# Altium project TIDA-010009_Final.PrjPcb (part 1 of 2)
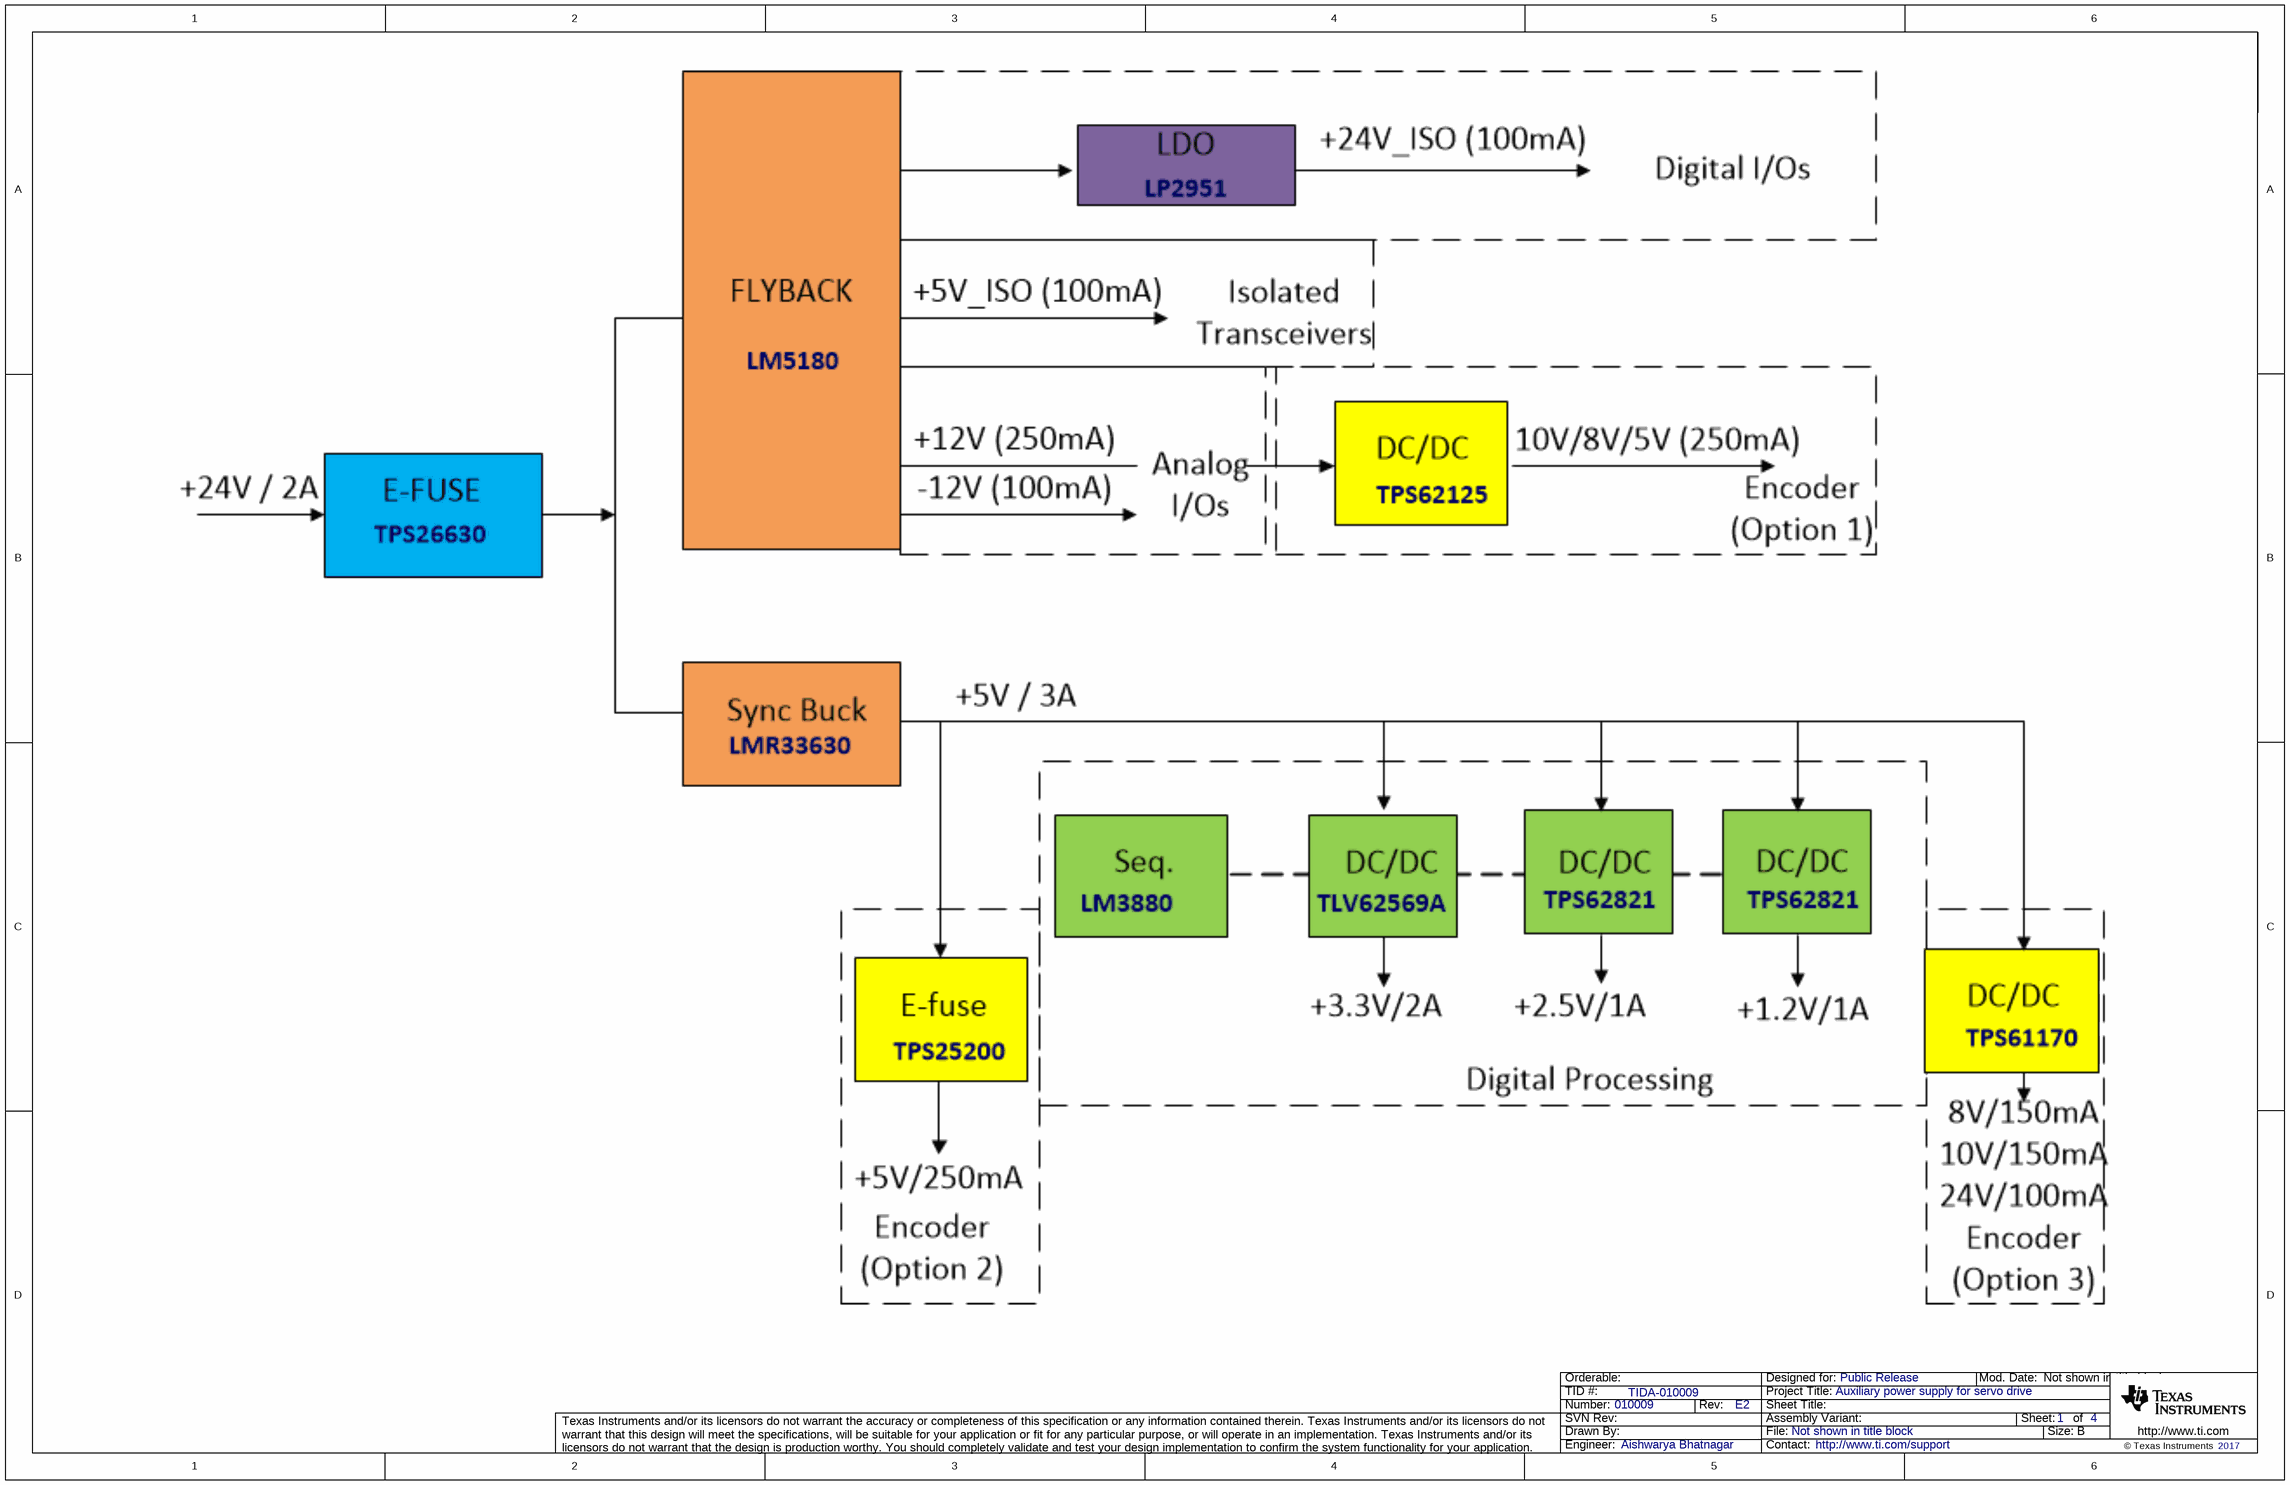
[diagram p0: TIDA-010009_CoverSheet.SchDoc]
CopyrightYear: 2017; PCB_Layout: Aishwarya; PCB_Rev: E2; PRJ_Customer: Public Release; PRJ_Engineer: Aishwarya Bhatnagar; PRJ_Number: 010009; PRJ_Title: Auxiliary power supply for servo drive; SCH_Rev: E2; TechSupport: http://www.ti.com/support; TID: TIDA-010009
4 sheets, 217 parts. Net scope: flat (ports and power ports of the same name join across sheets).
Board file: TIDA-010009_EVM_E2.PcbDoc
Sheets:
  TIDA-010009_CoverSheet.SchDoc
  Schematic1.SchDoc
  Schematic2.SchDoc
  TIDA-010009_EVM_Hardware.SchDoc

## Sheet TIDA-010009_CoverSheet.SchDoc
size 431 x 279 mm; Date: Not shown in title block; ApprovedBy: Not shown in title block; CheckedBy: Not shown in title block; Author: Not shown in title block; CompanyName: Not shown in title block; Engineer: Not shown in title block; Organization: Not shown in title block; Address1: Not shown in title block; Address2: Not shown in title block; Address3: Not shown in title block; Address4: Not shown in title block; DocumentNumber: 1; Revision: Use project parameter SCH_Rev; SheetNumber: 1; SheetTotal: 4; PageSetup: Record=PageOptions¦CenterHorizontal=True¦CenterVertical=True¦PrintScale=1.00¦XCorrection=1.00¦YCorrection=1.00¦PrintKind=0¦BorderSize=5000000¦LeftOffset=0¦BottomOffset=0¦Orientation=2¦PaperLength=1000¦PaperWidth=1000¦Scale=100¦PaperSource=15¦PrintQuality=600¦MediaType=1¦DitherType=10¦PaperKind=Letter¦PrintScaleMode=1

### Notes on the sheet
- Place Block Diagram here (if appropriate) or delete this text box.
  If using a block diagram from another tool, save the picture as a .bmp file.
  Then, use menu Place|Drawing Tools|Graphic to insert the .png/.svg/.bmp file on the schematic.

## Sheet Schematic1.SchDoc
size 431 x 279 mm; Date: Not shown in title block; ApprovedBy: Not shown in title block; CheckedBy: Not shown in title block; Author: Not shown in title block; CompanyName: Not shown in title block; Engineer: Not shown in title block; Organization: Not shown in title block; Address1: Not shown in title block; Address2: Not shown in title block; Address3: Not shown in title block; Address4: Not shown in title block; DocumentNumber: 1; Revision: Use project parameter SCH_Rev; SheetNumber: 2; SheetTotal: 4; PageSetup: Record=PageOptions¦CenterHorizontal=True¦CenterVertical=True¦PrintScale=1.00¦XCorrection=1.00¦YCorrection=1.00¦PrintKind=0¦BorderSize=5000000¦LeftOffset=0¦BottomOffset=0¦Orientation=2¦PaperLength=1000¦PaperWidth=1000¦Scale=100¦PaperSource=15¦PrintQuality=600¦MediaType=1¦DitherType=10¦PaperKind=Letter¦PrintScaleMode=1
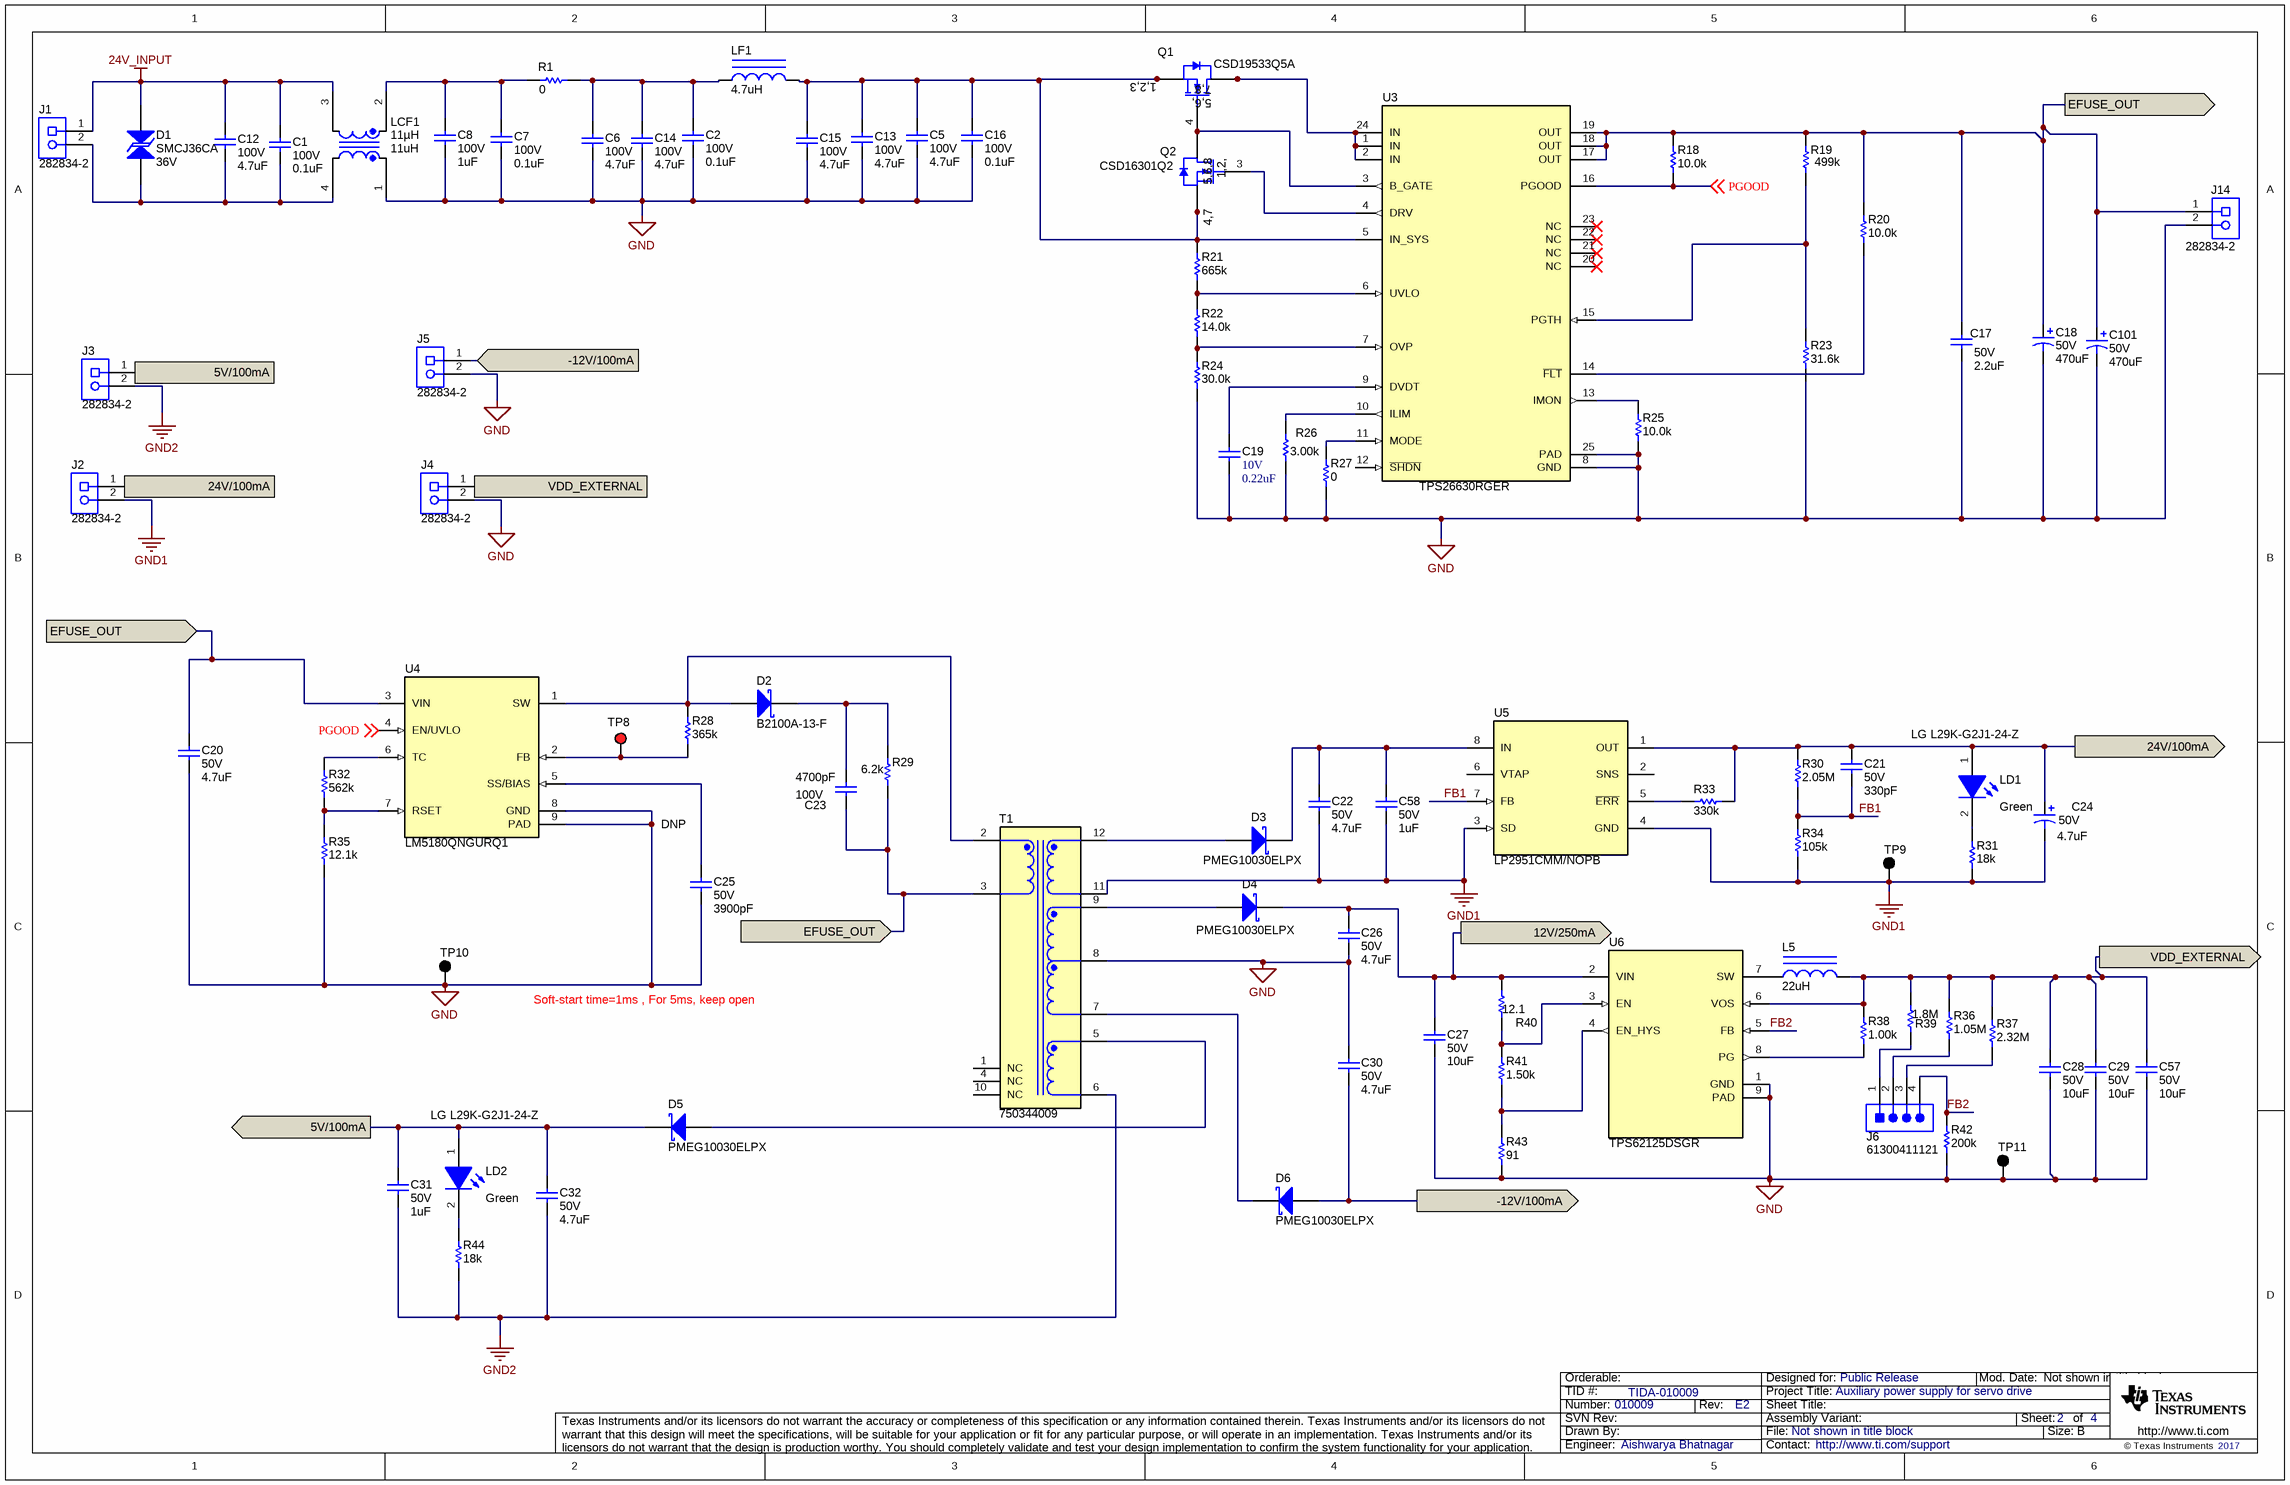
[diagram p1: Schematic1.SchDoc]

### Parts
C1  VDC_V: 100V  ValueDisplayed: 0.1uF  [0603]  (hidden comment: GCJ188R72A104KA01D)
C2  VDC_V: 100V  ValueDisplayed: 0.1uF  [0603]  (hidden comment: GCJ188R72A104KA01D)
C5  VDC_V: 100V  ValueDisplayed: 4.7uF  [1210]  (hidden comment: C3225X7S2A475K200AE)
C6  VDC_V: 100V  ValueDisplayed: 4.7uF  [1210]  (hidden comment: C3225X7S2A475K200AE)
C7  VDC_V: 100V  ValueDisplayed: 0.1uF  [0603]  (hidden comment: GCJ188R72A104KA01D)
C8  VDC_V: 100V  ValueDisplayed: 1uF  [0805_HV]  (hidden comment: C2012X7S2A105K125AB)
C12  VDC_V: 100V  ValueDisplayed: 4.7uF  [1210]  (hidden comment: C3225X7S2A475K200AE)
C13  VDC_V: 100V  ValueDisplayed: 4.7uF  [1210]  (hidden comment: C3225X7S2A475K200AE)
C14  VDC_V: 100V  ValueDisplayed: 4.7uF  [1210]  (hidden comment: C3225X7S2A475K200AE)
C15  VDC_V: 100V  ValueDisplayed: 4.7uF  [1210]  (hidden comment: C3225X7S2A475K200AE)
C16  VDC_V: 100V  ValueDisplayed: 0.1uF  [0603]  (hidden comment: GCJ188R72A104KA01D)
C17  VDC_V: 50V  ValueDisplayed: 2.2uF  [1206_180]  (hidden comment: C3216X7R1H225K160AB)
C18  VDC_V: 50V  ValueDisplayed: 470uF  [M_1000x2000]  (hidden comment: ECA-1HM471)
C19  VDC_V: 10V  ValueDisplayed: 0.22uF  [0603]  (hidden comment: GRM188R61A224KA01D)
C20  VDC_V: 50V  ValueDisplayed: 4.7uF  [1206_180]  (hidden comment: C3216X7R1H475K160AC)
C21  VDC_V: 50V  ValueDisplayed: 330pF  [0805_HV]  (hidden comment: C0805C331K5RACTU)
C22  VDC_V: 50V  ValueDisplayed: 4.7uF  [1206_180]  (hidden comment: C3216X7R1H475K160AC)
C23  VDC_V: 100V  ValueDisplayed: 4700pF  [0603]  (hidden comment: GCM188R72A472KA37D)
C24  VDC_V: 50V  ValueDisplayed: 4.7uF  [SM_RADIAL_C]  (hidden comment: EEE-FC1H4R7R)
C25  VDC_V: 50V  ValueDisplayed: 3900pF  [0603]  (hidden comment: GRM188R71H392KA01D)
C26  VDC_V: 50V  ValueDisplayed: 4.7uF  [1206_180]  (hidden comment: C3216X7R1H475K160AC)
C27  VDC_V: 50V  ValueDisplayed: 10uF  [1206_180]  (hidden comment: CL31B106KBHNNNE)
C28  VDC_V: 50V  ValueDisplayed: 10uF  [1206_180]  (hidden comment: CL31B106KBHNNNE)
C29  VDC_V: 50V  ValueDisplayed: 10uF  [1206_180]  (hidden comment: CL31B106KBHNNNE)
C30  VDC_V: 50V  ValueDisplayed: 4.7uF  [1206_180]  (hidden comment: C3216X7R1H475K160AC)
C31  VDC_V: 50V  ValueDisplayed: 1uF  [0805_HV]  (hidden comment: C0805C105K5RACTU)
C32  VDC_V: 50V  ValueDisplayed: 4.7uF  [1206_180]  (hidden comment: C3216X7R1H475K160AC)
C57  VDC_V: 50V  ValueDisplayed: 10uF  [1206_180]  (hidden comment: CL31B106KBHNNNE)
C58  VDC_V: 50V  ValueDisplayed: 1uF  [0805_HV]  (hidden comment: C0805C105K5RACTU)
C101  VDC_V: 50V  ValueDisplayed: 470uF  [M_1000x2000]  (hidden comment: ECA-1HM471)
D1  SMCJ36CA  value 36V  [SMC]
D2  B2100A-13-F  [SMA]
D3  PMEG10030ELPX  [SOD-128]
D4  PMEG10030ELPX  [SOD-128]
D5  PMEG10030ELPX  [SOD-128]
D6  PMEG10030ELPX  [SOD-128]
J1  282834-2  [TEC_282834-2]
J2  282834-2  [TEC_282834-2]
J3  282834-2  [TEC_282834-2]
J4  282834-2  [TEC_282834-2]
J5  282834-2  [TEC_282834-2]
J6  61300411121  [WURTH_61300411121]
J14  282834-2  [TEC_282834-2]
L5  ValueDisplayed: 22uH  [LPS4018]  (hidden comment: LPS4018-223MRB)
LCF1  value 11uH  ValueDisplayed: 11µH  [WE-SL5_HC]  (hidden comment: CMP-0076872-1)
LD1  LG L29K-G2J1-24-Z  value Green  [LG L29K_GREEN]
LD2  LG L29K-G2J1-24-Z  value Green  [LG L29K_GREEN]
LF1  ValueDisplayed: 4.7uH  [SRR1260]  (hidden comment: SRR1260-4R7Y)
Q1  CSD19533Q5A  [DQJ0008A]
Q2  CSD16301Q2  [DQK0006C]
R1  ValueDisplayed: 0  [1210]  (hidden comment: MCR25JZHJ000)
R18  ValueDisplayed: 10.0k  [0603]  (hidden comment: RG1608P-103-B-T5)
R19  ValueDisplayed: 499k  [0603]  (hidden comment: RT0603DRE07499KL)
R20  ValueDisplayed: 10.0k  [0603]  (hidden comment: RG1608P-103-B-T5)
R21  ValueDisplayed: 665k  [0603]  (hidden comment: RC0603FR-07665KL)
R22  ValueDisplayed: 14.0k  [0603]  (hidden comment: RC0603FR-0714KL)
R23  ValueDisplayed: 31.6k  [0603]  (hidden comment: RT0603BRD0731K6L)
R24  ValueDisplayed: 30.0k  [0603]  (hidden comment: RG1608P-303-B-T5)
R25  ValueDisplayed: 10.0k  [0603]  (hidden comment: RG1608P-103-B-T5)
R26  ValueDisplayed: 3.00k  [0603]  (hidden comment: RG1608P-302-B-T5)
R27  ValueDisplayed: 0  [0603]  (hidden comment: RMCF0603ZT0R00)
R28  ValueDisplayed: 365k  [0805_HV]  (hidden comment: CRCW0805365KFKEA)
R29  ValueDisplayed: 6.2k  [2512]  (hidden comment: CRCW25126K20JNEG)
R30  ValueDisplayed: 2.05M  [1206]  (hidden comment: RC1206FR-072M05L)
R31  ValueDisplayed: 18k  [0603]  (hidden comment: RC0603JR-0718KL)
R32  ValueDisplayed: 562k  [0603]  (hidden comment: RT0603DRE07562KL)
R33  ValueDisplayed: 330k  [0603]  (hidden comment: RC0603FR-07330KL)
R34  ValueDisplayed: 105k  [0603]  (hidden comment: RC0603FR-07105KL)
R35  ValueDisplayed: 12.1k  [0603]  (hidden comment: RT0603DRE0712K1L)
R36  ValueDisplayed: 1.05M  [0603]  (hidden comment: CRCW06031M05FKEA)
R37  ValueDisplayed: 2.32M  [0603]  (hidden comment: CRCW06032M32FKEA)
R38  ValueDisplayed: 1.00k  [0603]  (hidden comment: RT0603BRB071KL)
R39  ValueDisplayed: 1.8M  [0603]  (hidden comment: CRCW06031M80JNEA)
R40  ValueDisplayed: 12.1  [0805_HV]  (hidden comment: CRCW080512R1FKEA)
R41  ValueDisplayed: 1.50k  [0805_HV]  (hidden comment: RG2012P-152-B-T5)
R42  ValueDisplayed: 200k  [0805_HV]  (hidden comment: RG2012P-204-B-T5)
R43  ValueDisplayed: 91  [0805_HV]  (hidden comment: ERJ-6GEYJ910V)
R44  ValueDisplayed: 18k  [0603]  (hidden comment: RC0603JR-0718KL)
T1  750344009  [Wurth_EFD15_4265]
TP8  5000  [Keystone5000]  (value not drawn)
TP9  5001  [Keystone5001]  (value not drawn)
TP10  5001  [Keystone5001]  (value not drawn)
TP11  5001  [Keystone5001]  (value not drawn)
U3  TPS26630RGER  [RGE0024H]
U4  LM5180QNGURQ1  [NGU0008C]
U5  LP2951CMM/NOPB  [DGK0008A_N]
U6  TPS62125DSGR  [DSG0008A]

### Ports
5V/100mA (in), 5V/100mA (out), 12V/250mA (out), 24V/100mA (in), 24V/100mA (out), -12V/100mA (in), -12V/100mA (out), EFUSE_OUT (in), EFUSE_OUT (out), VDD_EXTERNAL (in), VDD_EXTERNAL (out)

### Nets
24V_INPUT: C1.2 C12.1 D1.2 J1.1 LCF1.3
GND: C2.1 C5.2 C6.2 C7.1 C8.2 C13.2 C14.2 C15.2 C16.1 C17.2 C18.2(-) C19.2 C20.2 C25.2 C26.1 C27.2 C28.2 C29.2 C30.2 C57.2 C101.2(-) J4.2 J5.2 J14.2 LCF1.1 R23.1 R24.1 R25.1 R26.1 R27.1 R35.1 R42.1 R43.1 T1.8 TP10.1 TP11.1 U3.8(GND) U3.25(PAD) U4.8(GND) U4.9(PAD) U6.1(GND) U6.9(PAD)
GND1: C22.2 C24.2(-) C58.2 J2.2 R31.1 R34.2 T1.11 TP9.1 U5.3(SD) U5.4(GND)
GND2: C31.1 C32.1 J3.2 R44.2 T1.6
5V/100mA: C31.2 C32.2 D5.1(K) J3.1 LD2.1(A) ; port 5V/100mA
12V/250mA: C26.2 C27.1 D4.1(K) R40.2 U6.2(VIN) ; port 12V/250mA
24V/100mA: C21.1 C24.1(+) J2.1 LD1.1(A) R30.1 R33.2 U5.1(OUT) ; port 24V/100mA
-12V/100mA: C30.1 D6.2(A) J5.1 ; port -12V/100mA
EFUSE_OUT: C17.1 C18.1(+) C20.1 C23.2 C101.1(+) J14.1 R18.2 R19.2 R20.2 R29.1 T1.3 U3.17(OUT) U3.18(OUT) U3.19(OUT) U4.3(VIN) ; port EFUSE_OUT
FB1: C21.2 R30.2 R34.1 U5.7(FB)
FB2: J6.4 R42.2 U6.5(FB)
PGOOD: R18.1 U3.16(PGOOD) U4.4(EN/UVLO) ; off-sheet PGOOD
VDD_EXTERNAL: C28.1 C29.1 C57.1 J4.1 L5.2 R36.2 R37.1 R38.2 R39.2 U6.6(VOS) ; port VDD_EXTERNAL
NetC1_1: C1.1 C12.2 D1.1 J1.2 LCF1.4
NetC2_2: C2.2 C6.1 C14.1 LF1.1 R1.2
NetC5_1: C5.1 C13.1 C15.1 C16.2 LF1.2 Q1.1(S) Q1.2(S) Q1.3(S) Q2.4(S) Q2.7(S) R21.2 U3.5(IN_SYS)
NetC7_2: C7.2 C8.1 LCF1.2 R1.1
NetC19_1: C19.1 U3.9(DVDT)
NetC22_1: C22.1 C58.1 D3.1(K) U5.8(IN)
NetC23_1: C23.1 D2.1(K) R29.2
NetC25_1: C25.1 U4.5(SS/BIAS)
NetD2_2: D2.2(A) R28.2 T1.2 U4.1(SW)
NetD3_2: D3.2(A) T1.12
NetD4_2: D4.2(A) T1.9
NetD5_2: D5.2(A) T1.5
NetD6_1: D6.1(K) T1.7
NetJ6_1: J6.1 R39.1
NetJ6_2: J6.2 R36.1
NetJ6_3: J6.3 R37.2
NetL5_1: L5.1 U6.7(SW)
NetLD1_2: LD1.2(K) R31.2
NetLD2_2: LD2.2(K) R44.1
NetQ1_4: Q1.4(G) Q2.1(D) Q2.2(D) Q2.5(D) Q2.6(D) Q2.8(D) U3.3(B_GATE)
NetQ1_5: Q1.5(D) Q1.6(D) Q1.7(D) Q1.8(D) Q1.9(D) U3.1(IN) U3.2(IN) U3.24(IN)
NetQ2_3: Q2.3(G) U3.4(DRV)
NetR19_1: R19.1 R23.2 U3.15(PGTH)
NetR20_1: R20.1 U3.14(~{FLT})
NetR21_1: R21.1 R22.2 U3.6(UVLO)
NetR22_1: R22.1 R24.2 U3.7(OVP)
NetR25_2: R25.2 U3.13(IMON)
NetR26_2: R26.2 U3.10(ILIM)
NetR27_2: R27.2 U3.11(MODE)
NetR28_1: R28.1 TP8.1 U4.2(FB)
NetR32_1: R32.1 R35.2 U4.7(RSET)
NetR32_2: R32.2 U4.6(TC)
NetR33_1: R33.1 U5.5(~{ERR})
NetR38_1: R38.1 U6.8(PG)
NetR40_1: R40.1 R41.2 U6.3(EN)
NetR41_1: R41.1 R43.2 U6.4(EN_HYS)

Not connected (* = marked no-connect by the designer): T1 1(NC) 4(NC) 10(NC); U3 12(~{SHDN}) 20(NC)* 21(NC)* 22(NC)* 23(NC)*; U5 2(SNS) 6(VTAP)

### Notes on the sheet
- DNP
- Soft-start time=1ms , For 5ms, keep open

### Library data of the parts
C1 C2 C7 C16 = CMP-0064935-4: CAP, CERM, 0.1 uF, 100 V,+/- 10%, X7R, AEC-Q200 Grade 1, 0603; Manufacturer: MuRata; TaMin_C: -55°C; Polarized: N; SizeAreaWB_mm2: 4.68; Value1: Unknown; U/M: EA; Value: 0.1uF; TaMax_C: 125°C; SizeZ_mm: 1; SizeX_mm: 1.6; SizeY_mm: 0.8; SizeArea_mm2: 1.28; AEC Qualified: Y; Cap_F: 100nF; AEC Category: Q200
C5 C6 C12-C15 = CMP-0009135-2: CAP, CERM, 4.7 uF, 100 V, +/- 10%, X7S, 1210; Manufacturer: TDK; TaMin_C: -55°C; Polarized: N; SizeAreaWB_mm2: 14.7; Value1: Unknown; U/M: EA; Value: 4.7uF; TaMax_C: 125°C; SizeZ_mm: 1.35; SizeX_mm: 3.2; SizeY_mm: 2.5; SizeArea_mm2: 8; Cap_F: 4.7µF; AEC Category: Q200
C8 = CMP-0007891-2: CAP, CERM, 1 uF, 100 V, +/- 10%, X7S, 0805; Manufacturer: TDK; TaMin_C: -55°C; ESR_ohm: 8.255m; Polarized: N; SizeAreaWB_mm2: 6.75; Value1: 0.008255 ohm; U/M: EA; Value: 1uF; TaMax_C: 125°C; SizeZ_mm: 1.45; SizeX_mm: 2; SizeY_mm: 1.25; Cap_Case: 0805; SizeArea_mm2: 2.5; Cap_F: 1µF; IRMS_A: 2.27442A; AEC Category: Q200
C17 = CMP-0008698-2: CAP, CERM, 2.2 uF, 50 V, +/- 10%, X7R, 1206; Manufacturer: TDK; TaMin_C: -55°C; ESR_ohm: 5.887m; Polarized: N; SizeAreaWB_mm2: 10.92; Value1: 0.005887 ohm; U/M: EA; Value: 2.2uF; TaMax_C: 125°C; SizeZ_mm: 1.8; SizeX_mm: 3.2; SizeY_mm: 1.6; SizeArea_mm2: 5.12; CompType: Capacitor; Cap_F: 2.2µF; IRMS_A: 2.99226A; AEC Category: Q200
C18 C101 = CMP-0009837-2: CAP, AL, 470 uF, 50 V, +/- 20%, TH; Manufacturer: Panasonic; TaMin_C: -40°C; Polarized: Y; SizeAreaWB_mm2: 144; Value1: Unknown; U/M: EA; Value: 470uF; TaMax_C: 85°C; SizeZ_mm: 22; SizeX_mm: 10; Cap_Case: 10x20mm; SizeArea_mm2: 100; CompType: Capacitor; Cap_F: 470µF; IRMS_A: 6.5dA; AEC Category: Q200
C19 = CMP-0007322-2: CAP, CERM, 0.22 uF, 10 V, +/- 10%, X5R, 0603; Manufacturer: MuRata; TaMin_C: -55°C; Polarized: N; SizeAreaWB_mm2: 4.68; Value1: Unknown; U/M: EA; Value: 0.22uF; TaMax_C: 85°C; SizeZ_mm: 1; SizeX_mm: 1.6; SizeY_mm: 0.8; SizeArea_mm2: 1.28; Cap_F: 220nF; AEC Category: Q200
C20 = CMP-0008702-2: CAP, CERM, 4.7 uF, 50 V, +/- 10%, X7R, 1206; Manufacturer: TDK; TaMin_C: -55°C; ESR_ohm: 3.158m; Polarized: N; SizeAreaWB_mm2: 10.92; Value1: 0.003158 ohm; U/M: EA; Value: 4.7uF; TaMax_C: 125°C; SizeZ_mm: 1.8; SizeX_mm: 3.2; SizeY_mm: 1.6; SizeArea_mm2: 5.12; CompType: Capacitor; Cap_F: 4.7µF; IRMS_A: 4.08379A; AEC Category: Q200
C21 = CMP-0007783-2: CAP, CERM, 330 pF, 50 V, +/- 10%, X7R, 0805; Manufacturer: Kemet; TaMin_C: -55°C; ESR_ohm: 9.35d; Polarized: N; SizeAreaWB_mm2: 6.75; Value1: 0.935 ohm; U/M: EA; Value: 330pF; TaMax_C: 125°C; SizeZ_mm: 1.45; SizeX_mm: 2; SizeY_mm: 1.25; Cap_Case: 0805; SizeArea_mm2: 2.5; IRMS_A: 1.67dA; AEC Category: Q200
C22 C26 C30 C32 = CMP-0008702-2: CAP, CERM, 4.7 uF, 50 V, +/- 10%, X7R, 1206; Manufacturer: TDK; TaMin_C: -55°C; ESR_ohm: 3.158m; Polarized: N; SizeAreaWB_mm2: 10.92; Value1: 0.003158 ohm; U/M: EA; Value: 4.7uF; TaMax_C: 125°C; SizeZ_mm: 1.8; SizeX_mm: 3.2; SizeY_mm: 1.6; SizeArea_mm2: 5.12; Cap_F: 4.7µF; IRMS_A: 4.08379A; AEC Category: Q200
C23 = CMP-0079247-1: CAP, CERM, 4700 pF, 100 V,+/- 10%, X7R, AEC-Q200 Grade 1, 0603; Manufacturer: MuRata; Cap_F: 4.7nF; SizeAreaWB_mm2: 4.68; SizeArea_mm2: 1.28; AEC Qualified: Y; AEC Category: Q200; Value: 4700pF; TaMax_C: 125°C; SizeZ_mm: 1; Polarized: N; TaMin_C: -55°C; SizeY_mm: 0.8; U/M: EA; SizeX_mm: 1.6
C24 = CMP-0011174-2: CAP, AL, 4.7 uF, 50 V, +/- 20%, 3 ohm, SMD; Manufacturer: Panasonic; TaMin_C: -40°C; ESR_ohm: 3; Polarized: Y; SizeAreaWB_mm2: 62.05; Value1: 3 ohm; U/M: EA; Value: 4.7uF; TaMax_C: 105°C; SizeZ_mm: 5.4; SizeX_mm: 6.5; SizeY_mm: 5.3; Cap_Case: C; SizeArea_mm2: 34.45; CompType: Capacitor; Cap_F: 4.7µF; IRMS_A: 50mA; AEC Category: Q200
C25 = CMP-0007453-4: CAP, CERM, 3900 pF, 50 V, +/- 10%, X7R, 0603; Manufacturer: MuRata; TaMin_C: -55°C; Polarized: N; SizeAreaWB_mm2: 4.68; Value1: Unknown; U/M: EA; Value: 3900pF; TaMax_C: 125°C; SizeZ_mm: 1; SizeX_mm: 1.6; SizeY_mm: 0.8; SizeArea_mm2: 1.28; CompType: Capacitor; Cap_F: 3.9nF; AEC Category: Q200
C27 C28 = CMP-0008802-2: CAP, CERM, 10 uF, 50 V, +/- 10%, X7R, 1206; Manufacturer: Samsung; TaMin_C: -55°C; Polarized: N; SizeAreaWB_mm2: 10.92; Value1: Unknown; U/M: EA; Value: 10uF; TaMax_C: 125°C; SizeZ_mm: 1.8; SizeX_mm: 3.2; SizeY_mm: 1.6; Cap_Case: 1206; SizeArea_mm2: 5.12; Cap_F: 10µF; AEC Category: Q200
C29 C57 = CMP-0008802-2: CAP, CERM, 10 uF, 50 V, +/- 10%, X7R, 1206; Manufacturer: Samsung; TaMin_C: -55°C; Polarized: N; SizeAreaWB_mm2: 10.92; Value1: Unknown; U/M: EA; Value: 10uF; TaMax_C: 125°C; SizeZ_mm: 1.8; SizeX_mm: 3.2; SizeY_mm: 1.6; Cap_Case: 1206; SizeArea_mm2: 5.12; CompType: Capacitor; Cap_F: 10µF; AEC Category: Q200
C31 = CMP-0007730-2: CAP, CERM, 1 uF, 50 V, +/- 10%, X7R, 0805; Manufacturer: Kemet; TaMin_C: -55°C; Polarized: N; SizeAreaWB_mm2: 6.75; Value1: Unknown; U/M: EA; Value: 1uF; TaMax_C: 125°C; SizeZ_mm: 1.45; SizeX_mm: 2; SizeY_mm: 1.25; Cap_Case: 0805; SizeArea_mm2: 2.5; CompType: Capacitor; Cap_F: 1µF; AEC Category: Q200
C58 = CMP-0007730-2: CAP, CERM, 1 uF, 50 V, +/- 10%, X7R, 0805; Manufacturer: Kemet; TaMin_C: -55°C; Polarized: N; SizeAreaWB_mm2: 6.75; Value1: Unknown; U/M: EA; Value: 1uF; TaMax_C: 125°C; SizeZ_mm: 1.45; SizeX_mm: 2; SizeY_mm: 1.25; Cap_Case: 0805; SizeArea_mm2: 2.5; Cap_F: 1µF; AEC Category: Q200
D1 = CMP-0005697-2: Diode, TVS, Bi, 36 V, 58.1 Vc, SMC; Manufacturer: Littelfuse; Power_W: 6.5W; SizeAreaWB_mm2: 83.2686; RJA_CperW: 75; U/M: EA; SizeZ_mm: 2.6; SizeX_mm: 8.13; SizeY_mm: 6.22; SizeArea_mm2: 50.5686; AEC Qualified: N; AEC Category: Q101
D2 = CMP-0081099-1: Diode, Schottky, 100 V, 2 A, SMA; Manufacturer: Diodes Inc.; SizeAreaWB_mm2: 37.3428; Vr_V: 100V; SizeArea_mm2: 16.3228; AEC Qualified: N; TJmax_C: 125°C; AEC Category: Q101; Value: 100V; SizeZ_mm: 2.87; Io_A: 2A; Vf_V: 7.9dV; SizeY_mm: 2.92; Value2: 0.79V; SizeX_mm: 5.59
D3-D6 = CMP-0028783-2: Diode, Schottky, 100 V, 3 A, AEC-Q101, SOD-128; Manufacturer: Nexperia; Io_A: 3A; Green_Lifecycle: Not Set; SizeAreaWB_mm2: 19.6; Vr_V: 100V; Green_REACh: Incomplete; TJmax_C: 175°C; U/M: EA; Value: 100V; SizeZ_mm: 1.1; SizeX_mm: 4.6; SizeY_mm: 2.5; Vf_V: 7.7dV; Value2: 0.77V; SizeArea_mm2: 11.5; AEC Qualified: Y; AEC Category: Q101
J1-J5 J14 = CMP-0054974-1: Terminal Block, 2x1, 2.54mm, TH; Manufacturer: TE Connectivity; CNHeader: FALSE; Green_Lifecycle: Active; Green_REACh: Passed; CT: TRUE
J6 = CMP-0054798-1: Header, 2.54 mm, 4x1, Gold, TH; Manufacturer: Wurth Elektronik; CNHeader: TRUE; CT: FALSE
L5 = CMP-0061350-2: Inductor, Shielded Drum Core, Ferrite, 22 uH, 0.83 A, 0.36 ohm, SMD; Manufacturer: Coilcraft; Isat: 0.83A @ 30% inductance drop; Irms: 0.9A @ 40C rise; Green_Lifecycle: Not Set; SizeAreaWB_mm2: 24.01; DCR_ohm: 3.6d; Green_REACh: Incomplete; Value: 22uH; Imax_A: 8.3dA; SizeZ_mm: 1.7; SizeX_mm: 3.9; Value2: 0.83A; SizeArea_mm2: 15.21; Ind_H: 22µH; AEC Qualified: N; AEC Category: Q200
LCF1 = CMP-0076872-1: Coupled inductor, 11 µH, 2.5 A, 0.03 ohm, SMD; PartNumber: 744273102; Manufacturer: Wurth Elektronik; DCR_ohm: 0.03; AEC Category: Q200
LD1 LD2 = CMP-0002874-1: LED, Green, SMD; Manufacturer: OSRAM; Io_A: 2mA; Tjmax_C: 110°C; Value1: W; U/M: EA; Vf_V: 1.7V
LF1 = CMP-0057094-1: Inductor, Drum Core, Ferrite, 4.7 uH, 6.8 A, 0.0155 ohm, SMD; Manufacturer: Bourns; Isat: 7A @ 25% inductance drop; Irms: 6.8A @ 40C rise; Green_Lifecycle: Active; SizeAreaWB_mm2: 210.25; DCR_ohm: 0.0155; Green_REACh: Passed; Value: 4.7uH; Imax_A: 6.8A; SizeZ_mm: 6; SizeX_mm: 12.5; SizeArea_mm2: 156.25; Ind_H: 4.7µH; AEC Category: Q200
Q1 = CMP-0000960-2: MOSFET, N-CH, 100 V, 13 A, DQJ0008A (VSONP-8); Alternate Manufacturer: None; Manufacturer: Texas Instruments; SizeZ_mm: 1.1; ChType: N; Value2: 27 nC; VdsMax_V: 100V; SizeX_mm: 6; SizeY_mm: 4.9; Vgs_V: 20V; QgTyp_nC: 27; Value: 100V; SizeArea_mm2: 29.4; AEC Category: Q101; IdsMax_A: 13A; SizeAreaWB_mm2: 55.2; U/M: EA
Q2 = CMP-0000248-1: MOSFET, N-CH, 25 V, 5 A, DQK0006C (WSON-6); Alternate Manufacturer: None; Manufacturer: Texas Instruments; SizeZ_mm: 0.8; ChType: N; Value2: 2 nC; Value1: 0.02; VdsMax_V: 25V; SizeX_mm: 2; Vgs_V: 10V; Value: 25V; Rdson45_ohm: 0.023; SizeArea_mm2: 4; AEC Category: Q101; IdsMax_A: 5A; SizeAreaWB_mm2: 9; U/M: EA
R1 = CMP-0015361-2: RES, 0, 5%, 0.25 W, 1210; Manufacturer: Rohm; Power_W: 250mW; TempCo: 20 ppm/C; SizeAreaWB_mm2: 14.7; Value_Code: 0000; U/M: EA; Value: 0; EIA_Code: E24; SizeX_mm: 3.2; SizeY_mm: 2.5; SizeZ_mm: 1.35; Value2: 0.25W; SizeArea_mm2: 8; VDC_V: 200V; AEC Category: Q200
R18 R25 = CMP-0023404-3: RES, 10.0 k, 0.1%, 0.1 W, 0603; Manufacturer: Susumu Co Ltd; Power_W: 100mW; TempCo: 25 ppm/C; Value_Code: 10k0; U/M: EA; Value: 10.0k; EIA_Code: E192; Res_ohm: 10k; SizeX_mm: 1.6; SizeY_mm: 0.8; SizeZ_mm: 1; Value2: 0.1W; SizeArea_mm2: 1.28; VDC_V: 75V; AEC Category: Q200
R19 = CMP-0025329-3: RES, 499 k, 0.5%, 0.1 W, 0603; Manufacturer: Yageo America; Power_W: 100mW; TempCo: 50 ppm/C; U/M: EA; Value: 499k; EIA_Code: E192; SizeX_mm: 1.6; SizeY_mm: 0.8; SizeZ_mm: 1; Value2: 0.1W; SizeArea_mm2: 1.28; CompType: Resistor; VDC_V: 75V; AEC Category: Q200
R20 = CMP-0023404-3: RES, 10.0 k, 0.1%, 0.1 W, 0603; Manufacturer: Susumu Co Ltd; Power_W: 100mW; TempCo: 25 ppm/C; Value_Code: 10k0; U/M: EA; Value: 10.0k; EIA_Code: E192; Res_ohm: 10k; SizeX_mm: 1.6; SizeY_mm: 0.8; SizeZ_mm: 1; Value2: 0.1W; SizeArea_mm2: 1.28; CompType: Resistor; VDC_V: 75V; AEC Category: Q200
R21 = CMP-0023230-4: RES, 665 k, 1%, 0.1 W, 0603; Manufacturer: Yageo; Power_W: 100mW; TempCo: 100 ppm/C; Value: 665k; EIA_Code: E96; SizeX_mm: 1.6; SizeY_mm: 0.8; SizeZ_mm: 1; Value2: 0.1W; SizeArea_mm2: 1.28; CompType: Resistor; AEC Qualified: N; VDC_V: 75V; AEC Category: Q200; SizeAreaWB_mm2: 4.68
R22 = CMP-0022804-5: RES, 14.0 k, 1%, 0.1 W, 0603; Manufacturer: Yageo; Power_W: 100mW; TempCo: 100 ppm/C; Value_Code: 14k0; Value: 14.0k; EIA_Code: E96; Res_ohm: 14k; SizeX_mm: 1.6; SizeY_mm: 0.8; SizeZ_mm: 1; Value2: 0.1W; SizeArea_mm2: 1.28; CompType: Resistor; AEC Qualified: N; VDC_V: 75V; AEC Category: Q200; SizeAreaWB_mm2: 4.68
R23 = CMP-0024107-3: RES, 31.6 k, 0.1%, 0.1 W, 0603; Manufacturer: Yageo America; Power_W: 100mW; TempCo: 25 ppm/C; Value_Code: 31k6; U/M: EA; Value: 31.6k; EIA_Code: E192; SizeX_mm: 1.6; SizeY_mm: 0.8; SizeZ_mm: 1; Value2: 0.1W; SizeArea_mm2: 1.28; VDC_V: 75V; AEC Category: Q200
R24 = CMP-0023508-3: RES, 30.0 k, 0.1%, 0.1 W, 0603; Manufacturer: Susumu Co Ltd; Power_W: 100mW; TempCo: 25 ppm/C; Value_Code: 30k0; U/M: EA; Value: 30.0k; Res_ohm: 30k; SizeX_mm: 1.6; SizeY_mm: 0.8; SizeZ_mm: 1; Value2: 0.1W; SizeArea_mm2: 1.28; VDC_V: 75V; AEC Category: Q200
R26 = CMP-0023507-3: RES, 3.00 k, 0.1%, 0.1 W, 0603; Manufacturer: Susumu Co Ltd; Power_W: 100mW; TempCo: 25 ppm/C; Value_Code: 3k00; U/M: EA; Value: 3.00k; Res_ohm: 3k; SizeX_mm: 1.6; SizeY_mm: 0.8; SizeZ_mm: 1; Value2: 0.1W; SizeArea_mm2: 1.28; CompType: Resistor; VDC_V: 75V; AEC Category: Q200
R27 = CMP-0023343-3: RES, 0, 1%, 0.1 W, AEC-Q200 Grade 0, 0603; Manufacturer: Stackpole Electronics Inc; Power_W: 100mW; TempCo: ppm/C; U/M: EA; Value: 0; SizeX_mm: 1.6; SizeY_mm: 0.8; SizeZ_mm: 1; Value2: 0.1W; SizeArea_mm2: 1.28; AEC Qualified: Y; AEC Category: Q200
R28 = CMP-0021190-4: RES, 365 k, 1%, 0.125 W, AEC-Q200 Grade 0, 0805; Manufacturer: Vishay-Dale; Power_W: 125mW; TempCo: 100 ppm/C; Value: 365k; EIA_Code: E96; SizeX_mm: 2; SizeY_mm: 1.25; SizeZ_mm: 1.45; Value2: 0.125W; SizeArea_mm2: 2.5; AEC Qualified: Y; VDC_V: 150V; AEC Category: Q200; AEC Grade: 0
R29 = CMP-0015996-3: RES, 6.2 k, 5%, 1 W, AEC-Q200 Grade 0, 2512; Manufacturer: Vishay-Dale; Power_W: 1W; TempCo: 200 ppm/C; Value_Code: 6k20; Value: 6.2k; EIA_Code: E24; SizeX_mm: 6.3; SizeY_mm: 3.2; SizeZ_mm: 0.71; SizeArea_mm2: 20.16; AEC Qualified: Y; VDC_V: 500V; AEC Grade: 0; AEC Category: Q200
R30 = CMP-0018159-2: RES, 2.05 M, 1%, 0.25 W, 1206; Manufacturer: Yageo America; Power_W: 250mW; TempCo: 100 ppm/C; Value_Code: 2M05; U/M: EA; Value: 2.05Meg; EIA_Code: E96; SizeX_mm: 3.2; SizeY_mm: 1.6; SizeZ_mm: 1.35; Value2: 0.25W; SizeArea_mm2: 5.12; VDC_V: 200V; AEC Category: Q200
R31 R44 = CMP-0025892-5: RES, 18 k, 5%, 0.1 W, 0603; Manufacturer: Yageo; Power_W: 100mW; TempCo: 100 ppm/C; Value_Code: 18k0; Value: 18k; EIA_Code: E24; SizeX_mm: 1.6; SizeY_mm: 0.8; SizeZ_mm: 1; Value2: 0.1W; SizeArea_mm2: 1.28; CompType: Resistor; AEC Qualified: N; VDC_V: 75V; AEC Category: Q200; SizeAreaWB_mm2: 4.68
R32 = CMP-0025409-3: RES, 562 k, 0.5%, 0.1 W, 0603; Manufacturer: Yageo America; Power_W: 100mW; TempCo: 50 ppm/C; U/M: EA; Value: 562k; EIA_Code: E192; SizeX_mm: 1.6; SizeY_mm: 0.8; SizeZ_mm: 1; Value2: 0.1W; SizeArea_mm2: 1.28; VDC_V: 75V; AEC Category: Q200
R33 = CMP-0023032-4: RES, 330 k, 1%, 0.1 W, 0603; Manufacturer: Yageo; Power_W: 100mW; TempCo: 100 ppm/C; Value: 330k; SizeX_mm: 1.6; SizeY_mm: 0.8; SizeZ_mm: 1; Value2: 0.1W; SizeArea_mm2: 1.28; AEC Qualified: N; VDC_V: 75V; AEC Category: Q200; SizeAreaWB_mm2: 4.68
R34 = CMP-0022739-4: RES, 105 k, 1%, 0.1 W, 0603; Manufacturer: Yageo; Power_W: 100mW; TempCo: 100 ppm/C; Value: 105k; EIA_Code: E96; SizeX_mm: 1.6; SizeY_mm: 0.8; SizeZ_mm: 1; Value2: 0.1W; SizeArea_mm2: 1.28; CompType: Resistor; AEC Qualified: N; VDC_V: 75V; AEC Category: Q200; SizeAreaWB_mm2: 4.68
R35 = CMP-0024637-3: RES, 12.1 k, 0.5%, 0.1 W, 0603; Manufacturer: Yageo America; Power_W: 100mW; TempCo: 50 ppm/C; Value_Code: 12k1; U/M: EA; Value: 12.1k; EIA_Code: E192; SizeX_mm: 1.6; SizeY_mm: 0.8; SizeZ_mm: 1; Value2: 0.1W; SizeArea_mm2: 1.28; VDC_V: 75V; AEC Category: Q200
R36 = CMP-0022140-4: RES, 1.05 M, 1%, 0.1 W, AEC-Q200 Grade 0, 0603; Manufacturer: Vishay-Dale; Power_W: 100mW; TempCo: 100 ppm/C; Value_Code: 1M05; Value: 1.05Meg; EIA_Code: E96; SizeX_mm: 1.6; SizeY_mm: 0.8; SizeZ_mm: 1; Value2: 0.1W; SizeArea_mm2: 1.28; AEC Qualified: Y; VDC_V: 75V; AEC Category: Q200; AEC Grade: 0
R37 = CMP-0022291-4: RES, 2.32 M, 1%, 0.1 W, AEC-Q200 Grade 0, 0603; Manufacturer: Vishay-Dale; Power_W: 100mW; TempCo: 100 ppm/C; Value_Code: 2M32; Value: 2.32Meg; EIA_Code: E96; SizeX_mm: 1.6; SizeY_mm: 0.8; SizeZ_mm: 1; Value2: 0.1W; SizeArea_mm2: 1.28; AEC Qualified: Y; VDC_V: 75V; AEC Category: Q200; AEC Grade: 0
R38 = CMP-0023629-3: RES, 1.00 k, 0.1%, 0.1 W, 0603; Manufacturer: Yageo America; Power_W: 100mW; TempCo: 10 ppm/C; Value_Code: 1k00; U/M: EA; Value: 1.00k; EIA_Code: E192; Res_ohm: 1k; SizeX_mm: 1.6; SizeY_mm: 0.8; SizeZ_mm: 1; Value2: 0.1W; SizeArea_mm2: 1.28; CompType: Resistor; AEC Qualified: N; VDC_V: 75V; AEC Category: Q200
R39 = CMP-0025742-4: RES, 1.8 M, 5%, 0.1 W, AEC-Q200 Grade 0, 0603; Manufacturer: Vishay-Dale; Power_W: 100mW; TempCo: 200 ppm/C; Value_Code: 1M80; Value: 1.8Meg; EIA_Code: E24; SizeX_mm: 1.6; SizeY_mm: 0.8; SizeZ_mm: 1; Value2: 0.1W; SizeArea_mm2: 1.28; AEC Qualified: Y; VDC_V: 75V; AEC Category: Q200; AEC Grade: 0
R40 = CMP-0020876-3: RES, 12.1, 1%, 0.125 W, AEC-Q200 Grade 0, 0805; Manufacturer: Vishay-Dale; Power_W: 125mW; TempCo: 100 ppm/C; Value_Code: 12R1; Value: 12.1; EIA_Code: E96; SizeX_mm: 2; SizeY_mm: 1.25; SizeZ_mm: 1.45; Value2: 0.125W; SizeArea_mm2: 2.5; AEC Qualified: Y; VDC_V: 150V; AEC Category: Q200; AEC Grade: 0
R41 = CMP-0018886-2: RES, 1.50 k, 0.1%, 0.125 W, 0805; Manufacturer: Susumu Co Ltd; Power_W: 125mW; TempCo: 25 ppm/C; Value_Code: 1k50; U/M: EA; Value: 1.50k; EIA_Code: E192; Res_ohm: 1.5k; SizeX_mm: 2; SizeY_mm: 1.25; SizeZ_mm: 1.45; Value2: 0.125W; SizeArea_mm2: 2.5; VDC_V: 100V; AEC Category: Q200
R42 = CMP-0018914-2: RES, 200 k, 0.1%, 0.125 W, 0805; Manufacturer: Susumu Co Ltd; U/M: EA; Value: 200k; EIA_Code: E192; SizeX_mm: 2; SizeY_mm: 1.25; SizeZ_mm: 1.45; Value2: 0.125W; SizeArea_mm2: 2.5; VDC_V: 100V; AEC Category: Q200; Power_W: 125mW; TempCo: 25 ppm/C
R43 = CMP-0020780-3: RES, 91, 5%, 0.125 W, AEC-Q200 Grade 0, 0805; Manufacturer: Panasonic; Power_W: 125mW; TempCo: 200 ppm/C; Value_Code: 91R0; Value: 91; EIA_Code: E24; SizeX_mm: 2; SizeY_mm: 1.25; SizeZ_mm: 1.45; Value2: 0.125W; SizeArea_mm2: 2.5; AEC Qualified: Y; VDC_V: 150V; AEC Category: Q200; AEC Grade: 0; SizeAreaWB_mm2: 6.75
T1 = CMP-0082441-1: Transformer, 75uH, SMT; Manufacturer: Wurth Elektronik; SizeAreaWB_mm2: 481.643; SizeArea_mm2: 397.383; AEC Qualified: N; Ns2toNp: 0.48; Lp: 75; AEC Category: Q200; SizeZ_mm: 8.89; Ind_H: 75µH; SizeY_mm: 17.78; Ns1toNp: 1; SizeX_mm: 22.35; Ns3toNp: 0.22
TP8 = CMP-0055137-1: Test Point, Miniature, Red, TH; Manufacturer: Keystone; CNHeader: FALSE; Green_Lifecycle: Active; Green_REACh: Passed; ContactFinish: Silver; CT: TRUE
TP9-TP11 = CMP-0055138-1: Test Point, Miniature, Black, TH; Manufacturer: Keystone; CNHeader: FALSE; Green_Lifecycle: Active; Green_REACh: Passed; ContactFinish: Silver; CT: TRUE
U3 = CMP-0080694-1: 4.5V - 60V, 6A 29mΩ eFuse with Reverse Polarity Protection, RGE0024H (VQFN-24); Alternate PartNumber: TPS26630RGET; Alternate Manufacturer: Texas Instruments; SizeAreaWB_mm2: 25; SizeZ_mm: 1; SizeX_mm: 4; SizeArea_mm2: 16; CompType: IC; AEC Qualified: N; AEC Category: Q200
U4 = CMP-0078633-2: 70-V PSR Flyback Converter With 100-V, 1.2-A Power Switch and Ultra-Low IQ, NGU0008C (WSON-8); Alternate PartNumber: LM5180QNGUTQ1; Alternate Manufacturer: Texas Instruments; SizeAreaWB_mm2: 25; SizeZ_mm: 0.8; SizeX_mm: 4; SizeArea_mm2: 16; CompType: IC; AEC Qualified: Y; AEC Category: Q200
U5 = CMP-0071033-2: Series of Adjustable Micropower Voltage Regulators, DGK0008A (VSSOP-8); Manufacturer: Texas Instruments; CompType: IC; AEC Category: Q200; AEC Qualified: N; SizeAreaWB_mm2: 23.6; SizeArea_mm2: 14.7; SizeX_mm: 4.9; SizeY_mm: 3; SizeZ_mm: 1.1
U6 = CMP-0067088-2: 3V-17V, 300mA Buck Converter With Adjustable Enable Threshold And Hysteresis, DSG0008A (WSON-8); Alternate PartNumber: TPS62125DSGT; Alternate Manufacturer: Texas Instruments; Green_Lifecycle: Active; SizeAreaWB_mm2: 9.0; Green_REACh: Passed; U/M: EA; SizeZ_mm: 0.8; SizeX_mm: 2.0; SizeArea_mm2: 4.0; CompType: IC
